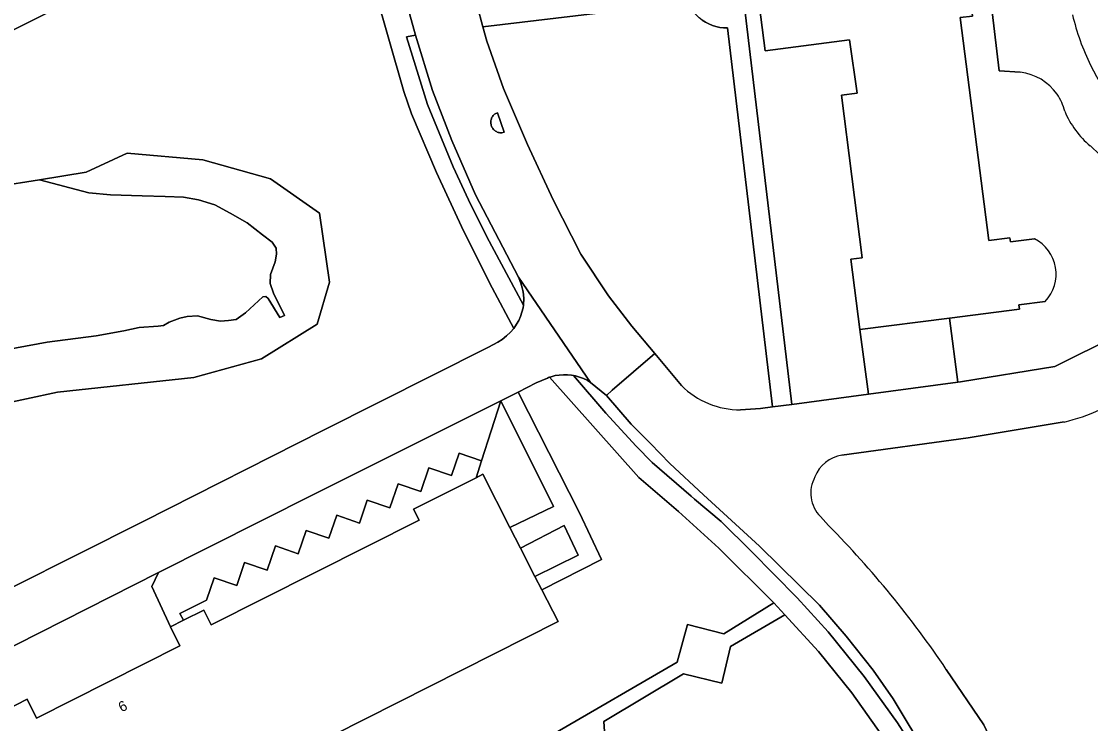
# Model space of a CAD drawing. Extents: x 158132 to 159664, y 385256 to 387218.
# Drawn here: x 159064.7 to 159168.9, y 386412 to 386480.5 of the extents above; entities that cross this region are included whole.
import ezdxf

# ---------------------------------------------------------------- set-up
doc = ezdxf.new("R2010")
doc.units = 0
for name, color, linetype in [('IMGEO_Berm_groen', 7, 'Continuous'), ('IMGEO_Groenvoorziening', 7, 'Continuous'), ('IMGEO_Meer_plas_ven_vijver', 7, 'Continuous'), ('IMGEO_Oever', 7, 'Continuous'), ('IMGEO_Pand', 7, 'Continuous'), ('IMGEO_Pand_nummerreeks', 7, 'Continuous'), ('IMGEO_Parkeervlak_open', 7, 'Continuous'), ('IMGEO_Rijbaan_lokaal_gesloten', 7, 'Continuous'), ('IMGEO_Rijbaan_lokaal_open', 7, 'Continuous'), ('IMGEO_Verkeerseiland_gesloten', 7, 'Continuous'), ('IMGEO_Voetpad_open', 7, 'Continuous')]:
    doc.layers.add(name, color=color, linetype=linetype)

msp = doc.modelspace()

# ---------------------------------------------------------------- linework, layer by layer
at = {"layer": 'IMGEO_Berm_groen'}
msp.add_lwpolyline([(159103.08, 386479.14), (159102.22, 386478.95), (159104.26, 386472.38), (159106.78, 386466.27), (159108.25, 386463.08), (159110.04, 386459.45), (159113.61, 386452.78), (159113.63, 386452.88), (159113.67, 386453.37), (159113.61, 386453.88), (159113.56, 386454.21), (159113.51, 386454.48), (159113.35, 386454.95), (159113.14, 386455.52), (159108.94, 386463.56), (159106.64, 386468.87), (159104.74, 386473.72)], close=True, dxfattribs=at)
msp.add_lwpolyline([(159153.06, 386408.77), (159149.66, 386414.41), (159147.72, 386417.19), (159145.08, 386420.52), (159142.5, 386423.55), (159136.63, 386429.28), (159131.19, 386434.28), (159127.9, 386437.35), (159126.02, 386439.29), (159124.12, 386441.2), (159121.72, 386444), (159120.17, 386445.26), (159119.82, 386445.47), (159119.46, 386445.64), (159119.09, 386445.78), (159118.7, 386445.89), (159118.59, 386445.91), (159118.49, 386445.93), (159121.65, 386442.26), (159124.62, 386439.03), (159126.16, 386437.44), (159129.98, 386434.15), (159130.31, 386433.87), (159132.89, 386431.69), (159135.82, 386428.79), (159140.3, 386424.26), (159143.34, 386420.92), (159146.84, 386416.59), (159150.09, 386412.07), (159153.08, 386407.38)], dxfattribs=at)
at = {"layer": 'IMGEO_Groenvoorziening'}
for points in [[(159130.94, 386517.43), (159139.8, 386443.12), (159147.26, 386444.12), (159146.41, 386450.43), (159145.54, 386457.28), (159146.66, 386457.42), (159144.64, 386473.29), (159146.15, 386473.48), (159145.42, 386478.66), (159137.19, 386477.61), (159135.51, 386490.77)], [(159156.38, 386515.26), (159153.92, 386514.96), (159153.96, 386514.58), (159151.92, 386514.32), (159153.74, 386500), (159154.68, 386492.67), (159155.92, 386492.83), (159156.46, 386488.53), (159156.91, 386485.02), (159157.42, 386480.99), (159156.22, 386480.84), (159158.99, 386459.1), (159161.05, 386459.36), (159161.1, 386458.96), (159163.46, 386459.26)], [(159057.35, 386422.06), (159076.55, 386431.69), (159094.11, 386440.59), (159110.07, 386448.64), (159110.2, 386448.7), (159111.12, 386449.17), (159111.56, 386449.46), (159111.98, 386449.8), (159112.36, 386450.17), (159112.67, 386450.53), (159110.57, 386454.48), (159107.78, 386460.06), (159105.15, 386465.72), (159102.7, 386471.45), (159101.94, 386473.64), (159099.08, 386483.66), (159095.79, 386495.63), (159058.61, 386477.03)], [(159162.07, 386475.51), (159160.01, 386475.65), (159159.1, 386483.35), (159160.04, 386483.48), (159159.98, 386484.13)], [(159134.79, 386442.58), (159136.74, 386442.71), (159137.91, 386442.87), (159133.51, 386479.83), (159133.13, 386479.84), (159132.76, 386479.89), (159132.39, 386479.96), (159132.04, 386480.08), (159131.69, 386480.22), (159131.36, 386480.39), (159131.05, 386480.59), (159130.75, 386480.82), (159130.48, 386481.08), (159130.23, 386481.35), (159130.01, 386481.66), (159129.81, 386481.98), (159129.64, 386482.31), (159109.67, 386479.93)], [(159109.67, 386479.93), (159110.05, 386478.53), (159111.67, 386473.93), (159114, 386468.46), (159116.52, 386463.07), (159119.22, 386457.77), (159121.92, 386453.72), (159124.19, 386450.76), (159126.43, 386448.09), (159129.03, 386444.96)], [(159174.8, 386461.48), (159172.42, 386464.95), (159168.9, 386468.32)], [(159062.28, 386464.36), (159066.42, 386465.03), (159070.99, 386465.77), (159074.99, 386467.61), (159082.36, 386466.96), (159088.96, 386465.12), (159093.72, 386461.76), (159094.7, 386455.04), (159093.51, 386450.93), (159088.09, 386447.57), (159081.49, 386445.73), (159068.17, 386444.32), (159059.08, 386442.37)], [(159164.51, 386453.16), (159161.94, 386452.84), (159161.99, 386452.41), (159155.18, 386451.54), (159155.98, 386445.28), (159156.24, 386445.32), (159165.45, 386446.82), (159171.51, 386449.85), (159174.31, 386453.59)], [(159116.76, 386411.07), (159128.6, 386417.97), (159129.63, 386421.66), (159133.16, 386420.73), (159138.05, 386423.77), (159132.68, 386429.11), (159128.73, 386432.67), (159124.87, 386435.99), (159116.15, 386445.76), (159116.05, 386445.73), (159115.95, 386445.69), (159114.87, 386445.21), (159113.09, 386444.32), (159119.08, 386432.55), (159121.23, 386428), (159115.41, 386425.03), (159116.99, 386421.94), (159091.98, 386409.3)], [(159166.34, 386441.4), (159156.97, 386439.87), (159144.68, 386438.18)], [(159142.57, 386432.17), (159143.37, 386431.29)], [(159148.62, 386410.76), (159145.65, 386414.99), (159142.39, 386419.01), (159139.11, 386422.6), (159133.82, 386419.51), (159132.95, 386415.93), (159129.24, 386416.83), (159121.47, 386412.18), (159121.61, 386409.78)], [(159154.85, 386417.26), (159158.5, 386411.85), (159159.6, 386409.6)]]:
    msp.add_lwpolyline(points, dxfattribs=at)
for points in [[(159111.4, 386443.47), (159109.52, 386437.62), (159109, 386435.97), (159109.65, 386436.3), (159112.3, 386431.12), (159116.54, 386433.17)], [(159103.45, 386431.83), (159102.91, 386432.89), (159109, 386435.97), (159109.52, 386437.62), (159107.35, 386438.36), (159107.34, 386438.35), (159106.6, 386436.18), (159104.39, 386436.93), (159103.6, 386434.62), (159101.39, 386435.37), (159100.59, 386433.03), (159098.38, 386433.78), (159097.62, 386431.54), (159095.41, 386432.3), (159094.64, 386430.06), (159092.43, 386430.81), (159091.66, 386428.55), (159089.45, 386429.31), (159088.64, 386426.94), (159086.43, 386427.69), (159085.66, 386425.44), (159083.46, 386426.19), (159082.72, 386424.03), (159080.11, 386422.73), (159080.46, 386422.06), (159082.45, 386423.06), (159083.18, 386421.62)], [(159113.33, 386429.1), (159114.74, 386426.33), (159118.97, 386428.4), (159117.58, 386431.3)]]:
    msp.add_lwpolyline(points, close=True, dxfattribs=at)
for centre, radius, start, end in [((159190.45, 386486.69), 23.95, 193.4594, 206.0015), ((159190.44, 386486.69), 23.94, 206.0142, 252.3223), ((159161.49, 386470.47), 5.07, 34.772, 83.437), ((159161.51, 386470.48), 5.05, 13.9839, 34.7896), ((159174.68, 386475.21), 8.99, 202.9473, 229.974), ((159161.68, 386455.82), 3.88, 316.8175, 62.6095), ((159134.78, 386450.73), 8.15, 225.1221, 270.0585), ((159162.41, 386458.34), 17.39, 283.0538, 307.5485), ((159145.18, 386434.85), 3.36, 98.6958, 159.2412), ((159144.93, 386434.47), 3.29, 151.3825, 224.3061), ((159073.64, 386362.54), 97.93, 33.976, 44.593)]:
    msp.add_arc(centre, radius, start, end, dxfattribs=at)
at = {"layer": 'IMGEO_Meer_plas_ven_vijver'}
for points in [[(159066.42, 386465.03), (159062.28, 386464.36), (159062.92, 386461.7), (159040.62, 386456.37), (159040.5, 386450.73), (159022.44, 386445.6), (159019.44, 386443.77), (159012.21, 386439.64)], [(159061.17, 386448.08), (159067.17, 386449.18), (159071.97, 386449.81), (159074.66, 386450.28), (159076.16, 386450.61), (159078, 386450.75), (159078.52, 386450.8), (159079.07, 386451.14), (159080.1, 386451.52), (159080.84, 386451.69), (159081.84, 386451.74), (159083.15, 386451.41), (159084.07, 386451.25), (159084.87, 386451.31), (159085.6, 386451.41), (159086.52, 386452.04), (159088.22, 386453.61), (159088.49, 386453.63), (159088.73, 386453.44), (159089.86, 386451.58), (159090.31, 386451.8), (159089.23, 386453.96), (159088.92, 386454.9), (159088.96, 386455.8), (159089.41, 386457.01), (159089.55, 386457.77), (159089.5, 386458.35), (159089.1, 386458.94), (159088.16, 386459.66), (159086.68, 386460.82), (159085.02, 386461.77), (159083.53, 386462.57), (159081.92, 386463.07), (159080.48, 386463.34), (159078.69, 386463.38), (159076.44, 386463.47), (159073.35, 386463.56), (159071.24, 386463.74), (159066.42, 386465.03)]]:
    msp.add_lwpolyline(points, dxfattribs=at)
at = {"layer": 'IMGEO_Oever'}
for points in [[(159068.17, 386444.32), (159081.49, 386445.73), (159088.09, 386447.57), (159093.51, 386450.93), (159094.7, 386455.04), (159093.72, 386461.76), (159088.96, 386465.12), (159082.36, 386466.96), (159074.99, 386467.61), (159070.99, 386465.77), (159066.42, 386465.03), (159071.24, 386463.74), (159073.35, 386463.56), (159076.44, 386463.47), (159078.69, 386463.38), (159080.48, 386463.34), (159081.92, 386463.07), (159083.53, 386462.57), (159085.02, 386461.77), (159086.68, 386460.82), (159088.16, 386459.66), (159089.1, 386458.94), (159089.5, 386458.35), (159089.55, 386457.77), (159089.41, 386457.01), (159088.96, 386455.8), (159088.92, 386454.9), (159089.23, 386453.96), (159090.31, 386451.8), (159089.86, 386451.58), (159088.73, 386453.44), (159088.49, 386453.63), (159088.22, 386453.61), (159086.52, 386452.04), (159085.6, 386451.41), (159084.87, 386451.31), (159084.07, 386451.25), (159083.15, 386451.41), (159081.84, 386451.74), (159080.84, 386451.69), (159080.1, 386451.52), (159079.07, 386451.14), (159078.52, 386450.8), (159078, 386450.75), (159076.16, 386450.61), (159074.66, 386450.28), (159071.97, 386449.81), (159067.17, 386449.18), (159061.17, 386448.08)], [(159012.21, 386439.64), (159019.44, 386443.77), (159022.44, 386445.6), (159020.33, 386450.04), (159011.8, 386444.98), (159005.17, 386440.01), (159002.13, 386435.24), (159000.8, 386431.97), (159000.77, 386428.72), (159001.86, 386425.64), (159006.56, 386420.41), (159008.93, 386418.79), (159011.48, 386417.94), (159014.2, 386417.9), (159017.17, 386418.5), (159020.21, 386419.95), (159037.76, 386432.56), (159042.9, 386435.88), (159059.08, 386442.37), (159068.17, 386444.32)]]:
    msp.add_lwpolyline(points, dxfattribs=at)
at = {"layer": 'IMGEO_Pand'}
for points in [[(159155.5, 386521.58), (159153.11, 386521.28), (159153.08, 386521.47), (159137.7, 386519.52), (159138.58, 386512.59), (159139.52, 386512.71), (159141.14, 386500), (159141.53, 386496.9), (159143.04, 386497.09), (159143.74, 386491.82), (159135.51, 386490.77), (159137.19, 386477.61), (159145.42, 386478.66), (159146.15, 386473.48), (159144.64, 386473.29), (159146.66, 386457.42), (159145.54, 386457.28), (159146.41, 386450.43), (159155.18, 386451.54), (159161.99, 386452.41), (159161.94, 386452.84), (159164.51, 386453.16)], [(159163.46, 386459.26), (159161.1, 386458.96), (159161.05, 386459.36), (159158.99, 386459.1), (159156.22, 386480.84), (159157.42, 386480.99), (159156.91, 386485.02), (159156.46, 386488.53)], [(159042.48, 386384.25), (159067.13, 386396.71), (159066.39, 386398.16), (159091.27, 386410.7), (159091.98, 386409.3), (159116.99, 386421.94), (159115.41, 386425.03), (159114.74, 386426.33), (159113.33, 386429.1), (159112.3, 386431.12), (159109.65, 386436.3), (159109, 386435.97), (159102.91, 386432.89), (159103.45, 386431.83), (159083.18, 386421.62), (159082.45, 386423.06), (159080.46, 386422.06), (159079.2, 386421.42), (159080.11, 386419.58), (159066.14, 386412.52), (159065.21, 386414.36), (159061.96, 386412.72)]]:
    msp.add_lwpolyline(points, dxfattribs=at)
msp.add_arc((159161.68, 386455.82), 3.88, 316.8175, 62.6095, dxfattribs=at)
at = {"layer": 'IMGEO_Parkeervlak_open'}
msp.add_lwpolyline([(159109.52, 386437.62), (159111.4, 386443.47), (159093.07, 386434.3), (159078.04, 386426.72), (159077.37, 386425.36), (159079.2, 386421.42), (159080.46, 386422.06), (159080.11, 386422.73), (159082.72, 386424.03), (159083.46, 386426.19), (159085.66, 386425.44), (159086.43, 386427.69), (159088.64, 386426.94), (159089.45, 386429.31), (159091.66, 386428.55), (159092.43, 386430.81), (159094.64, 386430.06), (159095.41, 386432.3), (159097.62, 386431.54), (159098.38, 386433.78), (159100.59, 386433.03), (159101.39, 386435.37), (159103.6, 386434.62), (159104.39, 386436.93), (159106.6, 386436.18), (159107.34, 386438.35), (159107.35, 386438.36)], close=True, dxfattribs=at)
at = {"layer": 'IMGEO_Rijbaan_lokaal_gesloten'}
for points in [[(159159.98, 386484.13), (159160.04, 386483.48), (159159.1, 386483.35), (159160.01, 386475.65), (159162.07, 386475.51)], [(159168.9, 386468.32), (159172.42, 386464.95), (159174.8, 386461.48), (159179.96, 386459.17), (159185.54, 386458.14), (159186.96, 386458.39)], [(159174.31, 386453.59), (159171.51, 386449.85), (159165.45, 386446.82), (159156.24, 386445.32), (159155.98, 386445.28), (159147.26, 386444.12), (159139.8, 386443.12), (159137.91, 386442.87), (159136.74, 386442.71), (159134.79, 386442.58)], [(159129.03, 386444.96), (159126.43, 386448.09), (159122.28, 386444.49), (159121.72, 386444), (159124.12, 386441.2), (159126.02, 386439.29), (159127.9, 386437.35), (159131.19, 386434.28), (159136.63, 386429.28), (159142.5, 386423.55), (159145.08, 386420.52), (159147.72, 386417.19), (159149.66, 386414.41), (159153.06, 386408.77), (159158.02, 386399.66), (159158.3, 386399.13), (159163.48, 386389.93), (159164.3, 386387.8), (159168.14, 386377.56), (159168.19, 386377.49), (159168.77, 386376.57), (159169.97, 386374.32)], [(159144.68, 386438.18), (159156.97, 386439.87), (159166.34, 386441.4)], [(159143.37, 386431.29), (159142.57, 386432.17)], [(159159.6, 386409.6), (159158.5, 386411.85), (159154.85, 386417.26)]]:
    msp.add_lwpolyline(points, dxfattribs=at)
for centre, radius, start, end in [((159190.45, 386486.69), 23.95, 193.4594, 206.0015), ((159190.44, 386486.69), 23.94, 206.0142, 252.3223), ((159161.49, 386470.47), 5.07, 34.772, 83.437), ((159161.51, 386470.48), 5.05, 13.9839, 34.7896), ((159174.68, 386475.21), 8.99, 202.9473, 229.974), ((159134.78, 386450.73), 8.15, 225.1221, 270.0585), ((159162.41, 386458.34), 17.39, 283.0538, 307.5485), ((159145.18, 386434.85), 3.36, 98.6958, 159.2412), ((159144.93, 386434.47), 3.29, 151.3825, 224.3061), ((159073.64, 386362.54), 97.93, 33.976, 44.593)]:
    msp.add_arc(centre, radius, start, end, dxfattribs=at)
at = {"layer": 'IMGEO_Rijbaan_lokaal_open'}
for points in [[(159102.52, 386481.25), (159103.08, 386479.14), (159104.74, 386473.72), (159106.64, 386468.87), (159108.94, 386463.56), (159113.14, 386455.52), (159120.17, 386445.26), (159121.72, 386444), (159122.28, 386444.49), (159126.43, 386448.09), (159124.19, 386450.76), (159121.92, 386453.72), (159119.22, 386457.77), (159116.52, 386463.07), (159114, 386468.46), (159111.67, 386473.93), (159110.05, 386478.53), (159109.67, 386479.93), (159109.11, 386482.01)], [(159061.77, 386418.51), (159078.04, 386426.72), (159093.07, 386434.3), (159111.4, 386443.47), (159113.09, 386444.32), (159114.87, 386445.21), (159115.95, 386445.69), (159116.05, 386445.73), (159116.15, 386445.76), (159116.33, 386445.82), (159116.71, 386445.92), (159117.11, 386445.98), (159117.51, 386446.01), (159117.91, 386446), (159118.31, 386445.96), (159118.49, 386445.93), (159118.59, 386445.91), (159118.7, 386445.89), (159119.09, 386445.78), (159119.46, 386445.64), (159119.82, 386445.47), (159120.17, 386445.26), (159113.14, 386455.52), (159113.35, 386454.95), (159113.51, 386454.48), (159113.56, 386454.21), (159113.61, 386453.88), (159113.67, 386453.37), (159113.63, 386452.88), (159113.61, 386452.78), (159113.58, 386452.52), (159113.47, 386452.1), (159113.33, 386451.7), (159113.16, 386451.3), (159112.95, 386450.93), (159112.67, 386450.53), (159112.36, 386450.17), (159111.98, 386449.8), (159111.56, 386449.46), (159111.12, 386449.17), (159110.2, 386448.7), (159110.07, 386448.64), (159094.11, 386440.59), (159076.55, 386431.69), (159057.35, 386422.06)]]:
    msp.add_lwpolyline(points, dxfattribs=at)
msp.add_lwpolyline([(159110.91, 386469.76), (159110.83, 386469.82), (159110.76, 386469.87), (159110.7, 386469.94), (159110.64, 386470.01), (159110.59, 386470.09), (159110.55, 386470.16), (159110.51, 386470.25), (159110.48, 386470.33), (159110.46, 386470.42), (159110.44, 386470.51), (159110.44, 386470.6), (159110.44, 386470.7), (159110.45, 386470.79), (159110.46, 386470.88), (159110.49, 386470.96), (159110.52, 386471.05), (159110.56, 386471.13), (159110.61, 386471.21), (159110.67, 386471.28), (159110.73, 386471.35), (159110.79, 386471.41), (159110.86, 386471.47), (159111.08, 386471.56), (159111.74, 386469.67), (159111.51, 386469.6), (159111.42, 386469.6), (159111.33, 386469.6), (159111.24, 386469.62), (159111.15, 386469.65), (159111.07, 386469.68), (159110.99, 386469.72)], close=True, dxfattribs=at)
at = {"layer": 'IMGEO_Verkeerseiland_gesloten'}
msp.add_lwpolyline([(159111.51, 386469.6), (159111.74, 386469.67), (159111.08, 386471.56), (159110.86, 386471.47), (159110.79, 386471.41), (159110.73, 386471.35), (159110.67, 386471.28), (159110.61, 386471.21), (159110.56, 386471.13), (159110.52, 386471.05), (159110.49, 386470.96), (159110.46, 386470.88), (159110.45, 386470.79), (159110.44, 386470.7), (159110.44, 386470.6), (159110.44, 386470.51), (159110.46, 386470.42), (159110.48, 386470.33), (159110.51, 386470.25), (159110.55, 386470.16), (159110.59, 386470.09), (159110.64, 386470.01), (159110.7, 386469.94), (159110.76, 386469.87), (159110.83, 386469.82), (159110.91, 386469.76), (159110.99, 386469.72), (159111.07, 386469.68), (159111.15, 386469.65), (159111.24, 386469.62), (159111.33, 386469.6), (159111.42, 386469.6)], close=True, dxfattribs=at)
at = {"layer": 'IMGEO_Voetpad_open'}
for points in [[(159131.05, 386480.59), (159131.36, 386480.39), (159131.69, 386480.22), (159132.04, 386480.08), (159132.39, 386479.96), (159132.76, 386479.89), (159133.13, 386479.84), (159133.51, 386479.83), (159137.91, 386442.87), (159139.8, 386443.12), (159130.94, 386517.43)], [(159058.61, 386477.03), (159095.79, 386495.63), (159095.26, 386497.85), (159094.35, 386500.3), (159092.88, 386499.58), (159084.68, 386495.44), (159081.74, 386501.24), (159072.77, 386496.72), (159074.74, 386492.79), (159055.65, 386483.24)], [(159099.08, 386483.66), (159101.94, 386473.64), (159102.7, 386471.45), (159105.15, 386465.72), (159107.78, 386460.06), (159110.57, 386454.48), (159112.67, 386450.53), (159112.95, 386450.93), (159113.16, 386451.3), (159113.33, 386451.7), (159113.47, 386452.1), (159113.58, 386452.52), (159113.61, 386452.78), (159110.04, 386459.45), (159108.25, 386463.08), (159106.78, 386466.27), (159104.26, 386472.38), (159102.22, 386478.95), (159103.08, 386479.14), (159102.52, 386481.25)], [(159109.11, 386482.01), (159109.67, 386479.93), (159129.64, 386482.31)], [(159153.08, 386407.38), (159150.09, 386412.07), (159146.84, 386416.59), (159143.34, 386420.92), (159140.3, 386424.26), (159135.82, 386428.79), (159132.89, 386431.69), (159130.31, 386433.87), (159129.98, 386434.15), (159126.16, 386437.44), (159124.62, 386439.03), (159121.65, 386442.26), (159118.49, 386445.93), (159118.31, 386445.96), (159117.91, 386446), (159117.51, 386446.01), (159117.11, 386445.98), (159116.71, 386445.92), (159116.33, 386445.82), (159116.15, 386445.76), (159124.87, 386435.99), (159128.73, 386432.67), (159132.68, 386429.11), (159138.05, 386423.77), (159139.11, 386422.6), (159142.39, 386419.01), (159145.65, 386414.99), (159148.62, 386410.76)], [(159121.61, 386409.78), (159121.47, 386412.18), (159129.24, 386416.83), (159132.95, 386415.93), (159133.82, 386419.51), (159139.11, 386422.6), (159138.05, 386423.77), (159133.16, 386420.73), (159129.63, 386421.66), (159128.6, 386417.97), (159116.76, 386411.07)]]:
    msp.add_lwpolyline(points, dxfattribs=at)
for points in [[(159155.18, 386451.54), (159146.41, 386450.43), (159147.26, 386444.12), (159155.98, 386445.28)], [(159113.09, 386444.32), (159111.4, 386443.47), (159116.54, 386433.17), (159112.3, 386431.12), (159113.33, 386429.1), (159117.58, 386431.3), (159118.97, 386428.4), (159114.74, 386426.33), (159115.41, 386425.03), (159121.23, 386428), (159119.08, 386432.55)], [(159079.2, 386421.42), (159077.37, 386425.36), (159078.04, 386426.72), (159061.77, 386418.51), (159063.74, 386414.56), (159061.58, 386413.48), (159061.96, 386412.72), (159065.21, 386414.36), (159066.14, 386412.52), (159080.11, 386419.58)]]:
    msp.add_lwpolyline(points, close=True, dxfattribs=at)

# ---------------------------------------------------------------- texts
at = {"layer": 'IMGEO_Pand_nummerreeks'}
msp.add_text('6', height=1, rotation=27.1525, dxfattribs=at).set_placement((159074.44, 386413.07))

doc.saveas('drawing.dxf')
